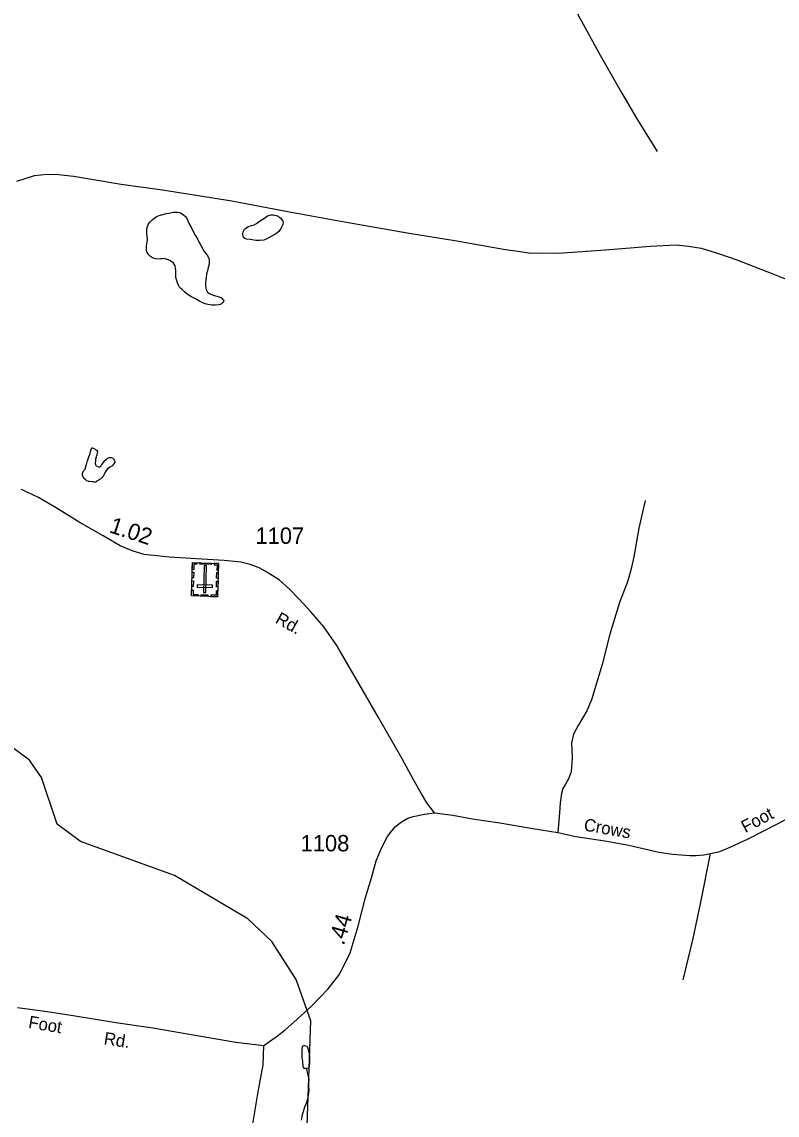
# Model space of a CAD drawing. Extents: x 2206922 to 2357709, y 510027 to 673830.
# Drawn here: x 2235957 to 2241724, y 541278 to 549625 of the extents above; entities that cross this region are included whole.
import ezdxf

# ---------------------------------------------------------------- set-up
doc = ezdxf.new("R2010")
doc.units = 0
for name, color, linetype in [('Exist Cultural Cemetery CELL', 7, 'Continuous'), ('Exist Hydrographic Creek Single Shore', 7, 'Continuous'), ('Exist Hydrographic Misc Water Feature', 7, 'Continuous'), ('Exist Road Non-System Type 51', 7, 'Continuous'), ('Exist Road Secondary Mileage Hundredths English Label', 7, 'Continuous'), ('Exist Road Secondary Type 51 Attributed', 7, 'Continuous'), ('Exist Road Secondary Type 51 Label', 7, 'Continuous'), ('Exist Road Secondary Type 51 Number Label', 7, 'Continuous')]:
    doc.layers.add(name, color=color, linetype=linetype)

msp = doc.modelspace()

# ---------------------------------------------------------------- linework, layer by layer
at = {"layer": 'Exist Cultural Cemetery CELL'}
for points in [[(2237451.1, 545236.3), (2237252.1, 545242.4), (2237259.9, 545496.9), (2237458.9, 545490.8)], [(2237293, 545495.9), (2237292.7, 545484.4), (2237270.7, 545485), (2237269.5, 545444.7), (2237258.3, 545445), (2237259.9, 545496.9)], [(2237401.1, 545481.1), (2237316.3, 545483.7), (2237316.6, 545495.1), (2237401.5, 545492.5)], [(2237343.1, 545268.9), (2237361.7, 545268.3), (2237367.9, 545471), (2237349.2, 545471.6)], [(2237425.8, 545491.8), (2237425.5, 545480.3), (2237447.5, 545479.6), (2237446.2, 545439.2), (2237457.4, 545438.9), (2237459, 545490.7)], [(2237269.1, 545424.3), (2237267.7, 545381), (2237256.4, 545381.3), (2237257.7, 545424.6)], [(2237456.8, 545420.9), (2237455.5, 545377.6), (2237444.1, 545377.9), (2237445.4, 545421.2)], [(2237267, 545358.4), (2237265.7, 545315.1), (2237254.3, 545315.4), (2237255.6, 545358.7)], [(2237412.4, 545305.6), (2237413, 545324.2), (2237295.3, 545327.8), (2237294.7, 545309.1)], [(2237454.7, 545353.7), (2237453.4, 545310.4), (2237442, 545310.8), (2237443.4, 545354)], [(2237253.4, 545285.7), (2237264.7, 545285.4), (2237263.8, 545253.2), (2237304.3, 545252), (2237304, 545240.8), (2237252.1, 545242.4)], [(2237377.1, 545238.6), (2237325.3, 545240.1), (2237325.6, 545251.5), (2237377.4, 545250)], [(2237452.5, 545279.6), (2237441.1, 545279.9), (2237440.1, 545247.7), (2237399.6, 545249), (2237399.3, 545237.9), (2237451.1, 545236.3)]]:
    msp.add_lwpolyline(points, close=True, dxfattribs=at)
at = {"layer": 'Exist Hydrographic Creek Single Shore'}
msp.add_lwpolyline([(2238109.5, 540472.8), (2238163.4, 541996.9), (2238052.4, 542314), (2237866.5, 542603.1), (2237682.3, 542777.3), (2237121.3, 543106.8), (2236403.4, 543367.2), (2236227.3, 543498.7), (2236107.3, 543855.3), (2236015.3, 543988.4), (2235688.4, 544227.9), (2235469.4, 544432.3), (2235292.2, 544688.5), (2235099.3, 544879.3), (2234890.3, 544968.8), (2234148.3, 545046.1), (2233815.3, 545144.7), (2233028.3, 545521.3), (2232828.3, 545561.4), (2231371.2, 545456.3), (2231221.3, 545488.8), (2230446.2, 546665.6), (2228706.2, 546536.6), (2228754.2, 545669.8)], dxfattribs=at)
at = {"layer": 'Exist Hydrographic Misc Water Feature'}
for points in [[(2237213.6, 548128.4), (2237237.6, 548078.5), (2237254, 548046.9), (2237266.1, 548024.8), (2237280.6, 547997), (2237292.5, 547976.9), (2237302.8, 547959.2), (2237310.8, 547941.4), (2237318.6, 547927.2), (2237333.1, 547899.5), (2237347.5, 547875.4), (2237361.6, 547855.8), (2237375.8, 547835.9), (2237383.8, 547818), (2237385.8, 547812), (2237387.9, 547802), (2237388.1, 547789.8), (2237386, 547775.9), (2237380.1, 547750), (2237374.5, 547723.7), (2237366.8, 547697.7), (2237362.9, 547674), (2237361, 547655.6), (2237359.2, 547629.9), (2237359.2, 547611.7), (2237361.4, 547591.8), (2237363.5, 547581.8), (2237369.6, 547572), (2237375.6, 547562.2), (2237383.6, 547554.1), (2237395.9, 547548.2), (2237411.9, 547540.4), (2237436.1, 547534.4), (2237464.2, 547526.9), (2237482, 547516.9), (2237490, 547508.8), (2237496.1, 547503), (2237498.2, 547497), (2237496.3, 547490.8), (2237490.4, 547482.8), (2237480.6, 547472.9), (2237470.7, 547466.7), (2237460.5, 547464.6), (2237432.6, 547462.4), (2237406.5, 547462.2), (2237376.6, 547465.9), (2237356.3, 547471.8), (2237338.5, 547479.7), (2237314.1, 547491.5), (2237282.3, 547509.3), (2237248, 547529.1), (2237219.9, 547546.7), (2237198, 547562.6), (2237179.7, 547580.4), (2237169.5, 547590.4), (2237161.3, 547600.1), (2237153.5, 547614.3), (2237145.3, 547632.1), (2237139.1, 547648.1), (2237132.8, 547673.8), (2237132.8, 547699.8), (2237132.6, 547723.7), (2237130.3, 547745.9), (2237128.3, 547756), (2237126.4, 547766), (2237120.1, 547773.8), (2237114.1, 547783.7), (2237100, 547795.6), (2237085.8, 547803.3), (2237065.5, 547811.3), (2237043.6, 547817.4), (2237030.1, 547817), (2237017.5, 547816.9), (2236990.1, 547814.5), (2236977.8, 547814.8), (2236966.1, 547818.6), (2236955.6, 547822.6), (2236947.6, 547828.2), (2236939.8, 547834.3), (2236931.8, 547842.4), (2236921.4, 547852.1), (2236913.8, 547864.2), (2236909.3, 547876.2), (2236907.4, 547889.9), (2236909.1, 547909.9), (2236911.3, 547933.9), (2236915, 547956), (2236916.7, 547974), (2236912.4, 548001.8), (2236910.3, 548017.9), (2236911.9, 548038), (2236913.8, 548053.9), (2236917.9, 548067.9), (2236923.6, 548082.1), (2236933.7, 548096), (2236951.5, 548112.3), (2236965.1, 548124.5), (2236983.3, 548136.3), (2236993.4, 548140.5), (2237005, 548146.8)], [(2237005, 548146.8), (2237033.1, 548154.8), (2237060.8, 548161.1), (2237081.1, 548165.4), (2237112.9, 548171.5), (2237130.7, 548171.7), (2237144.7, 548172), (2237156.8, 548169.8), (2237168.9, 548165.9), (2237189, 548154.4), (2237205.4, 548140.2), (2237213.6, 548128.4)], [(2237950.9, 548092.5), (2237949.1, 548078.6), (2237945.4, 548066.6), (2237933.5, 548046.1), (2237917.9, 548024.1), (2237903.6, 548012.1), (2237889.6, 548002.1), (2237846.2, 547977.8), (2237828.1, 547967.6), (2237804.3, 547959.3), (2237772.6, 547956.9), (2237742.2, 547957), (2237700.4, 547962.5), (2237672.5, 547966.3), (2237658.5, 547972), (2237650.1, 547978.2), (2237645.8, 547988.1), (2237644.2, 547998.1), (2237644.2, 548005.8), (2237647.7, 548019.9), (2237652, 548031.8), (2237657.7, 548041.9), (2237663.5, 548047.9), (2237683.4, 548060.3), (2237711, 548070.4), (2237731.1, 548076.6), (2237747.3, 548086.8), (2237771.3, 548103), (2237791, 548117.1), (2237810.9, 548129.1), (2237832.8, 548143.6), (2237848.8, 548149.7), (2237860.9, 548151.5), (2237876.7, 548152), (2237886.6, 548149.7), (2237899.1, 548147.8), (2237913, 548142.1), (2237922.6, 548134.2), (2237934.5, 548126.3), (2237940.9, 548116.4), (2237949.3, 548104.6), (2237950.9, 548092.5)], [(2236493.8, 546373.6), (2236488.1, 546367.6), (2236484.2, 546359.2), (2236478.3, 546341.5), (2236472.3, 546319.2), (2236466.4, 546301.5), (2236460.6, 546287.4), (2236454.7, 546269.2), (2236451, 546257.2), (2236449.1, 546243.3), (2236443, 546227.2), (2236441.4, 546219.3), (2236439.5, 546211.1), (2236433.6, 546203), (2236429, 546197.2), (2236423.5, 546189.1), (2236419.6, 546180.8), (2236417.8, 546175), (2236417.6, 546160.8), (2236421.7, 546152.9), (2236427.8, 546143.1), (2236440.1, 546133.1), (2236451.6, 546123.3), (2236462.1, 546117.2), (2236474, 546117.5), (2236496.3, 546115.7), (2236512.1, 546111.7), (2236520.1, 546113.7), (2236531.8, 546119.7), (2236541.8, 546125.9), (2236548, 546129.8), (2236555.8, 546135.9), (2236563.8, 546140), (2236575.7, 546150.4), (2236581.6, 546160.4), (2236591.2, 546178.4), (2236597.6, 546190.5), (2236605.4, 546202.3), (2236617.1, 546218.4), (2236624.9, 546224.5), (2236631.2, 546228.8), (2236641.1, 546232.6), (2236647, 546234.9), (2236651.1, 546238.8), (2236658.9, 546246.9), (2236668.8, 546260.8), (2236670.6, 546267), (2236664.7, 546276.8), (2236660.6, 546282.7), (2236658.7, 546286.7), (2236654.6, 546290.9), (2236648, 546294.8), (2236640.3, 546296.7), (2236632.3, 546296.7), (2236626.3, 546296.4), (2236620.4, 546296.5), (2236614.4, 546294.6), (2236604.6, 546286.3), (2236594.3, 546278.5), (2236584.5, 546270.3), (2236574.8, 546258.3), (2236564.8, 546246.1), (2236559.3, 546236), (2236555, 546228.1), (2236550.9, 546224.3), (2236545.3, 546225.9), (2236539.2, 546228), (2236527.1, 546233.9), (2236523.2, 546235.8), (2236521.1, 546239.7), (2236520.9, 546243.8), (2236519.1, 546249.8), (2236518.9, 546261.5), (2236521.1, 546269.7), (2236522.6, 546285.7), (2236522.8, 546289.8), (2236524.6, 546296), (2236526.2, 546303.8), (2236528.1, 546309.6), (2236530.5, 546313.7), (2236532.4, 546322), (2236534.4, 546331.8), (2236535.9, 546345.7), (2236532.2, 546351.6), (2236526.2, 546353.7), (2236518.2, 546359.8), (2236507.8, 546365.4), (2236499.8, 546369.4), (2236493.8, 546373.6)], [(2238116.2, 541807), (2238108, 541807), (2238102.1, 541804.6), (2238098, 541802.8), (2238096.3, 541792.5), (2238094.5, 541778.6), (2238094.7, 541764.8), (2238094.7, 541754.7), (2238094.7, 541734.8), (2238094.9, 541720.5), (2238094.9, 541714.9), (2238097.1, 541702.8), (2238099.4, 541690.7), (2238100.8, 541674.7), (2238101.5, 541664.9), (2238103.3, 541650.8), (2238105.3, 541644.8), (2238107.6, 541640.8), (2238113.3, 541635), (2238127.7, 541636.9)], [(2238127.7, 541636.9), (2238147.8, 541639.2), (2238151.1, 541647.2), (2238153.3, 541655), (2238155.2, 541673.4), (2238155.2, 541689.2), (2238155.2, 541697.3), (2238155, 541713.2), (2238154.8, 541725.3), (2238152.5, 541747.1), (2238148.8, 541763.1), (2238142.5, 541789.2), (2238138.4, 541797.1), (2238134.3, 541801), (2238126.1, 541804.7), (2238116.2, 541807)], [(2238127.7, 541636.9), (2238135.9, 541606.9), (2238143.9, 541573.3), (2238148, 541549.1), (2238146.2, 541525.1), (2238144.9, 541497.3), (2238146.8, 541465.3), (2238143.1, 541427), (2238135.7, 541391.2), (2238127.5, 541367.3), (2238116, 541339), (2238104.5, 541303.1), (2238096.1, 541280.8), (2238088.9, 541240.9)]]:
    msp.add_lwpolyline(points, dxfattribs=at)
at = {"layer": 'Exist Road Non-System Type 51'}
for points in [[(2240198.8, 549685.3), (2240373.1, 549370.6), (2240537.4, 549081.5), (2240656.3, 548876), (2240775.3, 548689), (2240807.9, 548635.8)], [(2235918, 548407.6), (2236053.3, 548450.8), (2236149.1, 548462.1), (2236235.6, 548460.2), (2236352.1, 548447.1), (2236489.3, 548424.5), (2236714.8, 548386.9), (2237030.5, 548343.6), (2237559.7, 548259.2), (2238000.1, 548174.7), (2238420.6, 548098.2), (2238913.1, 548012.3), (2239263.2, 547955), (2239633.6, 547890.1), (2239761.8, 547871.1), (2239843.9, 547857.9), (2239927.7, 547860.6), (2240051.7, 547859.5), (2240413.3, 547884.4), (2240757, 547913.2), (2240952.7, 547922.8), (2241046.9, 547913.5), (2241142.9, 547898.4), (2241283.2, 547853.6), (2241415.5, 547808.7), (2241690.2, 547701), (2241983, 547585.3)], [(2240714.9, 545971.9), (2240668.6, 545759.5), (2240628.4, 545539.4), (2240607.2, 545439.2), (2240580, 545349), (2240521.2, 545192.6), (2240445.4, 544950), (2240387.1, 544717.7), (2240305.4, 544449.2), (2240270.1, 544364.9), (2240205, 544252.5), (2240169.7, 544186.2), (2240154.2, 544120.2), (2240159.1, 544006.3), (2240151.9, 543898.3), (2240134.4, 543852), (2240108.9, 543806), (2240087, 543771.8), (2240077.4, 543733.6), (2240068, 543661.6), (2240060.7, 543585.6), (2240049.8, 543435.7)], [(2241006.5, 542312), (2241083.7, 542626.6), (2241140.4, 542905.4), (2241214.4, 543274.9)]]:
    msp.add_lwpolyline(points, dxfattribs=at)
at = {"layer": 'Exist Road Secondary Type 51 Attributed'}
for points in [[(2239107.9, 543584.9), (2239049.9, 543663.1), (2239008, 543730), (2238945.1, 543843.7), (2238859.7, 543998.5), (2238680.8, 544313.8), (2238558.3, 544525), (2238361.7, 544863.6), (2238263.4, 545007.2), (2238166.7, 545118.4), (2238074.8, 545218.4), (2238000.7, 545295), (2237921.7, 545366), (2237815.3, 545431.3), (2237768.6, 545456.3), (2237699.3, 545481.3), (2237630, 545499), (2237501, 545513.5), (2237330.2, 545523.2), (2237085.2, 545539.3), (2236891.8, 545559.5), (2236808, 545583.7), (2236708.1, 545625.6), (2236577.6, 545699.8), (2236395.4, 545804.6), (2236218.1, 545915.9), (2236084.4, 545994.9), (2235953.8, 546054.5)], [(2237805.7, 541808.6), (2237909.5, 541883.1), (2237966.8, 541928.8), (2238032.9, 541986.8), (2238169.5, 542109), (2238296.4, 542242), (2238376.2, 542347.2), (2238413.3, 542411.7), (2238464.8, 542518.2), (2238524.5, 542721.4), (2238580.9, 542939.1), (2238625.3, 543090.3), (2238662.3, 543218.5), (2238703.5, 543316.8), (2238748.6, 543405.1), (2238782.3, 543449.4), (2238809.7, 543481.7), (2238856.5, 543517.2), (2238904.8, 543546.2), (2238945.1, 543557.5), (2239032.1, 543576.8), (2239107.9, 543584.9)], [(2239107.9, 543584.9), (2239246.5, 543567.1), (2239398, 543541.3), (2239607.5, 543510), (2239857.7, 543466.1), (2240049.8, 543435.7), (2240186, 543406.7), (2240408.3, 543372.7), (2240592.3, 543340.2), (2240820.6, 543286.6), (2240925.7, 543271.6), (2241055.9, 543261.6), (2241105.9, 543261.6), (2241164.3, 543266.6), (2241214.4, 543274.9), (2241286.4, 543291.8), (2241370, 543326.5), (2241497.6, 543385.5), (2241626.9, 543452.5), (2241791.2, 543534.9)], [(2235922.4, 542099.5), (2236131.9, 542072.1), (2236349.5, 542038.2), (2236675.1, 541985), (2236957.1, 541944.7), (2237279.5, 541889.9), (2237589.7, 541836.1), (2237805.7, 541808.6)], [(2237892.5, 538959.4), (2237891.3, 538979.2), (2237883, 539058.5), (2237864.1, 539149.6), (2237847.5, 539208.8), (2237795.5, 539323.5), (2237754.7, 539419.4), (2237726.3, 539481.5), (2237699.7, 539568.5), (2237674.9, 539696.2), (2237650, 539847.1), (2237623.4, 539998), (2237595, 540159.5), (2237582.6, 540305), (2237579.1, 540386.6), (2237580.9, 540471.8), (2237611.9, 540625.3), (2237653.9, 540877.3), (2237702.1, 541103.7), (2237725.1, 541241.8), (2237762.1, 541456.3), (2237799.2, 541662.7), (2237805.7, 541808.6)]]:
    msp.add_lwpolyline(points, dxfattribs=at)

# ---------------------------------------------------------------- texts
at = {"layer": 'Exist Road Secondary Mileage Hundredths English Label'}
for s, rotation, p in [('1.02', 342.03234, (2236617.6, 545729.1)), ('.44', 73.64376, (2238414.7, 542569.3))]:
    msp.add_text(s, height=125, rotation=rotation, dxfattribs=at).set_placement(p)
at = {"layer": 'Exist Road Secondary Type 51 Label'}
for s, rotation, p in [('Rd.', 331.15923, (2237885, 545040.6)), ('Foot', 28.02946, (2241480.8, 543430.5)), ('Crows', 349.98328, (2240242.7, 543451.9)), ('Foot', 350.5473, (2236002.4, 541944.6)), ('Rd.', 351.1452, (2236578.4, 541819.9))]:
    msp.add_text(s, height=95, rotation=rotation, dxfattribs=at).set_placement(p)
at = {"layer": 'Exist Road Secondary Type 51 Number Label'}
for s, p in [('1107', (2237740.7, 545639.8)), ('1108', (2238085.3, 543292.1))]:
    msp.add_text(s, height=125, dxfattribs=at).set_placement(p)

doc.saveas('drawing.dxf')
